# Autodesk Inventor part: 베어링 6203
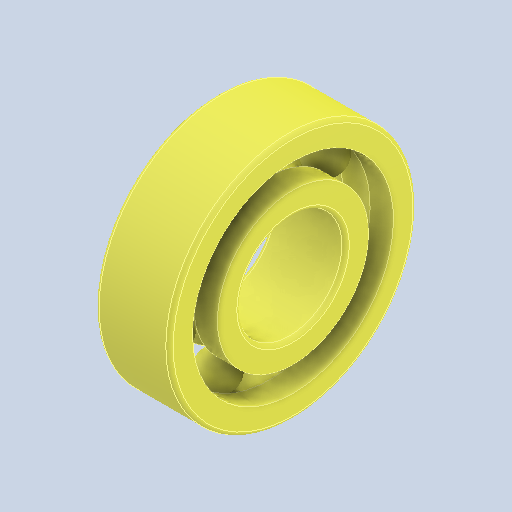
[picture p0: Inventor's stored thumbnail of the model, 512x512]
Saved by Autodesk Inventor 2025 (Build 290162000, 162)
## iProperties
Created: 2024-07
Part Number: 베어링 6203
Material: 강철, 연강
Description: 깊은 그루브 볼 베어링
Document SubType Name: Modeling
Designer: SAMSUNG
Density: 7.86 g/cm^3
Appearance: 기본값
Author: jhkim
Revision Number: 1
Sending System: Autodesk Inventor 2025
Preprocessor: ST-DEVELOPER v20
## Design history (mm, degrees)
feature "Solid1"
feature "Solid1:1"
feature "Solid1:2"
feature "Solid1:3"
feature "Solid1:4"
feature "Solid1:5"
feature "Solid1:6"
feature "Solid1:7"
feature "Solid1:8"
node "솔리드1"
node "솔리드2"
node "솔리드3"
node "솔리드4"
node "솔리드5"
node "솔리드6"
node "솔리드7"
node "솔리드8"
node "솔리드9"
